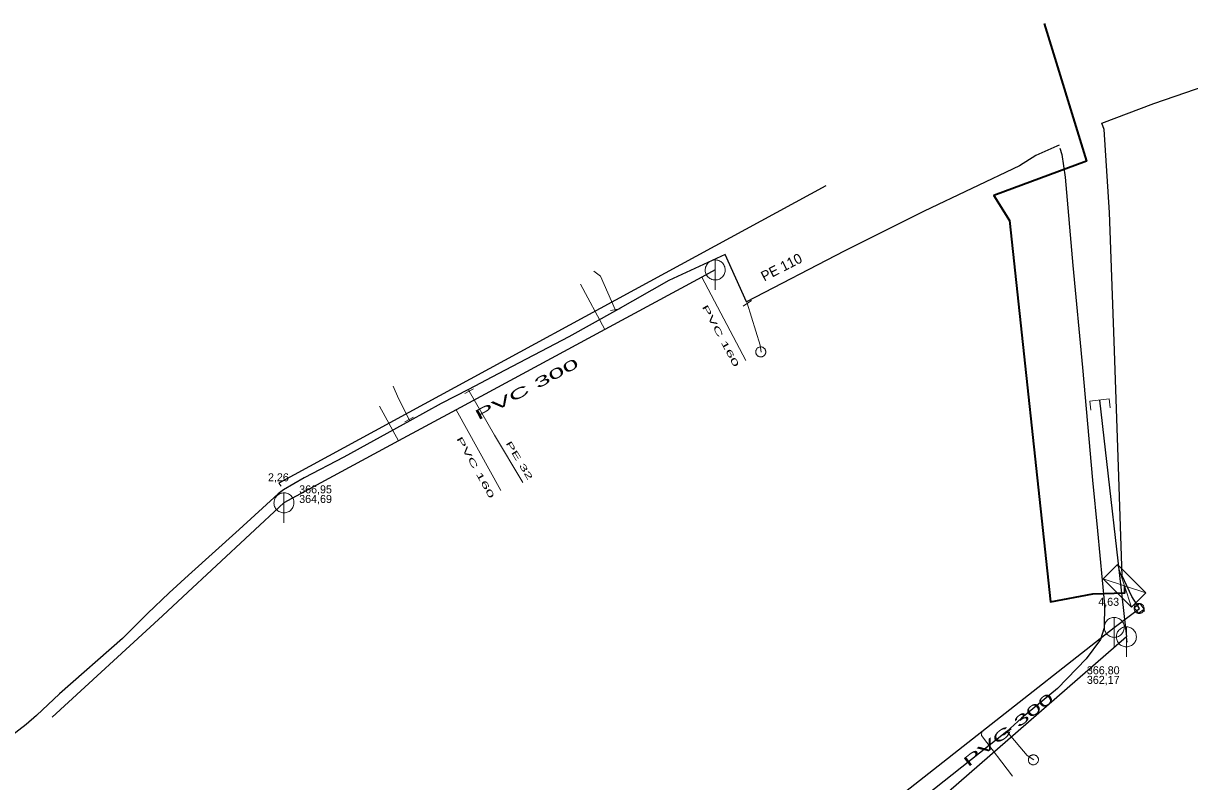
# Model space of a CAD drawing. Extents: x -809916 to -809489, y -991143 to -990912.
# Drawn here: x -809837.8 to -809721.2, y -990987.3 to -990911.5 of the extents above; entities that cross this region are included whole.
import ezdxf

# ---------------------------------------------------------------- set-up
doc = ezdxf.new("R2010")
doc.units = 0
doc.header["$LTSCALE"] = 0.32
doc.header["$PDMODE"] = 32
doc.header["$PDSIZE"] = 0.16
doc.layers.add('1', color=7, linetype='Continuous')
for name, color, linetype, lineweight in [('11', 7, 'Continuous', 13), ('13', 7, 'Continuous', 13), ('14', 7, 'Continuous', 25), ('17', 7, 'Continuous', 25), ('19', 7, 'Continuous', 13), ('22', 7, 'Continuous', 13), ('23', 7, 'Continuous', 13), ('31', 7, 'Continuous', 13), ('34', 7, 'Continuous', 13), ('4', 7, 'Continuous', 13)]:
    doc.layers.add(name, color=color, linetype=linetype, lineweight=lineweight)

msp = doc.modelspace()

# ---------------------------------------------------------------- linework, layer by layer
at = {"layer": '11'}
for p, q in [((-809765.559, -990945.19), (-809769.96, -990936.87)), ((-809782.09, -990937.559), (-809779.66, -990942.109)), ((-809802.17, -990949.76), (-809800.28, -990953.239)), ((-809790.05, -990958.199), (-809794.52, -990950.129)), ((-809812, -990957.75), (-809812.23, -990957.46)), ((-809727.44, -990973.35), (-809727.52, -990972.809))]:
    msp.add_line(p, q, dxfattribs=at)
at = {"layer": '11', "lineweight": 35}
msp.add_lwpolyline([(-809735.753, -990911.51), (-809731.52, -990925.268), (-809740.78, -990928.707), (-809739.192, -990931.221), (-809735.091, -990969.321), (-809730.858, -990968.527), (-809727.683, -990968.395), (-809727.683, -990967.733)], dxfattribs=at)
at = {"layer": '11'}
msp.add_lwpolyline([(-809738.899, -990986.73), (-809742.01, -990982.67), (-809741.98, -990982.27)], dxfattribs=at)
at = {"layer": '13'}
for points in [[(-809778.609, -990940.11), (-809780.1, -990936.78), (-809780.77, -990936.28)], [(-809765.41, -990939.48), (-809764.129, -990943.67), (-809764.039, -990944.359)], [(-809799.219, -990951.09), (-809800.28, -990949), (-809800.809, -990947.75)], [(-809793.219, -990948.26), (-809790.699, -990952.67), (-809787.84, -990957.379)], [(-809739.42, -990982.309), (-809737.44, -990984.66), (-809736.78, -990985.09)]]:
    msp.add_lwpolyline(points, dxfattribs=at)
at = {"layer": '14'}
for p, q in [((-809757.55, -990927.76), (-809812.23, -990957.46)), ((-809730.21, -990949.149), (-809727.52, -990972.809))]:
    msp.add_line(p, q, dxfattribs=at)
at = {"layer": '14', "lineweight": 13}
for p, q in [((-809765.5, -990939.35), (-809765.41, -990939.48)), ((-809778.59, -990940.219), (-809778.609, -990940.11)), ((-809793.3, -990948.11), (-809793.219, -990948.26)), ((-809799.219, -990951.09), (-809799.16, -990951.21)), ((-809739.469, -990982.25), (-809739.42, -990982.309))]:
    msp.add_line(p, q, dxfattribs=at)
at = {"layer": '14'}
for points in [[(-809726.219, -990969.96), (-809726.98, -990968.78), (-809727.949, -990966.71), (-809728.3, -990955.809), (-809728.739, -990943.25), (-809729.199, -990930.399), (-809729.739, -990922.109), (-809729.96, -990921.489), (-809724.76, -990919.53), (-809718.469, -990917.359), (-809710.05, -990914.129), (-809708.579, -990913.68), (-809706.219, -990913.69), (-809699.82, -990914.32), (-809692.859, -990914.989), (-809688.989, -990915.219), (-809679.469, -990915.67), (-809679.19, -990916.14), (-809678.829, -990917.93), (-809676.92, -990922.699), (-809676.27, -990924.289), (-809674.469, -990928.55)], [(-809768.62, -990936.149), (-809769.96, -990936.87), (-809779.66, -990942.109), (-809794.52, -990950.129), (-809800.28, -990953.239), (-809811.73, -990959.42)], [(-809811.73, -990959.42), (-809821.84, -990968.8), (-809823.879, -990970.699), (-809834.89, -990980.82)], [(-809728.73, -990971.86), (-809727.12, -990970.64), (-809726.219, -990969.96)], [(-809754.89, -990992.42), (-809741.98, -990982.27), (-809728.73, -990971.86)], [(-809727.52, -990972.809), (-809749.16, -990991.649), (-809753.69, -990995.359), (-809765.379, -991004.55)]]:
    msp.add_lwpolyline(points, dxfattribs=at)
at = {"layer": '17'}
for points in [[(-809734.239, -990923.69), (-809734.469, -990923.77), (-809736.57, -990924.73), (-809738.21, -990925.75), (-809747.719, -990930.27), (-809755.719, -990934.26), (-809765.5, -990939.35), (-809767.64, -990934.6)], [(-809734.16, -990923.969), (-809733.96, -990924.629), (-809733.649, -990926.879), (-809732.87, -990935.71), (-809731.899, -990945.899), (-809730.91, -990957.17), (-809730.39, -990962.23), (-809729.719, -990969.61), (-809729.73, -990971.899), (-809730.109, -990973.059), (-809731.53, -990975.01), (-809734.39, -990977.98), (-809737.989, -990980.949), (-809739.469, -990982.25), (-809748.46, -990989.399)], [(-809767.64, -990934.6), (-809773.26, -990937.219), (-809778.59, -990940.219), (-809783.25, -990942.84), (-809790.329, -990946.53), (-809793.3, -990948.11), (-809796.01, -990949.51), (-809799.16, -990951.21), (-809805.73, -990954.85), (-809809.719, -990956.93), (-809811.77, -990958.109), (-809812.32, -990958.52), (-809816.21, -990962.07), (-809821.28, -990966.66), (-809823.19, -990968.42), (-809825.359, -990970.469), (-809827.879, -990972.96), (-809834.17, -990978.5), (-809836.469, -990980.68), (-809837.489, -990981.55), (-809839.26, -990982.92)]]:
    msp.add_lwpolyline(points, dxfattribs=at)
at = {"layer": '19'}
for p, q in [((-809727.008, -990969.835), (-809728.411, -990965.578)), ((-809725.581, -990968.408), (-809729.838, -990967.005))]:
    msp.add_line(p, q, dxfattribs=at)
msp.add_lwpolyline([(-809727.008, -990969.835), (-809729.838, -990967.005), (-809728.411, -990965.578), (-809725.581, -990968.408)], close=True, dxfattribs=at)
at = {"layer": '22'}
for p, q in [((-809768.62, -990938.149), (-809768.619, -990935.149)), ((-809811.73, -990961.42), (-809811.729, -990958.42)), ((-809728.73, -990973.86), (-809728.729, -990970.86)), ((-809727.52, -990974.809), (-809727.519, -990971.809))]:
    msp.add_line(p, q, dxfattribs=at)
for points in [[(-809767.62, -990936.149), (-809767.625, -990936.04), (-809767.643, -990935.932), (-809767.673, -990935.826), (-809767.713, -990935.725), (-809767.765, -990935.628), (-809767.827, -990935.538), (-809767.899, -990935.455), (-809767.979, -990935.381), (-809768.067, -990935.315), (-809768.161, -990935.26), (-809768.261, -990935.215), (-809768.366, -990935.182), (-809768.473, -990935.16), (-809768.582, -990935.15), (-809768.692, -990935.152), (-809768.8, -990935.166), (-809768.907, -990935.191), (-809769.01, -990935.228), (-809769.108, -990935.277), (-809769.2, -990935.335), (-809769.286, -990935.404), (-809769.363, -990935.481), (-809769.432, -990935.567), (-809769.491, -990935.659), (-809769.539, -990935.757), (-809769.576, -990935.86), (-809769.602, -990935.967), (-809769.616, -990936.075), (-809769.619, -990936.185), (-809769.609, -990936.294), (-809769.588, -990936.401), (-809769.554, -990936.505), (-809769.51, -990936.605), (-809769.455, -990936.7), (-809769.389, -990936.788), (-809769.315, -990936.868), (-809769.232, -990936.94), (-809769.142, -990937.002), (-809769.046, -990937.054), (-809768.944, -990937.095), (-809768.839, -990937.125), (-809768.731, -990937.143), (-809768.621, -990937.149), (-809768.512, -990937.143), (-809768.404, -990937.125), (-809768.299, -990937.096), (-809768.197, -990937.055), (-809768.1, -990937.003), (-809768.01, -990936.941), (-809767.927, -990936.87), (-809767.852, -990936.79), (-809767.787, -990936.702), (-809767.731, -990936.608), (-809767.687, -990936.508), (-809767.653, -990936.404), (-809767.631, -990936.296), (-809767.621, -990936.187)], [(-809810.73, -990959.42), (-809810.735, -990959.311), (-809810.753, -990959.203), (-809810.783, -990959.097), (-809810.823, -990958.996), (-809810.875, -990958.899), (-809810.937, -990958.809), (-809811.009, -990958.726), (-809811.089, -990958.652), (-809811.177, -990958.586), (-809811.271, -990958.531), (-809811.371, -990958.486), (-809811.476, -990958.453), (-809811.583, -990958.431), (-809811.692, -990958.421), (-809811.802, -990958.423), (-809811.91, -990958.437), (-809812.017, -990958.462), (-809812.12, -990958.499), (-809812.218, -990958.548), (-809812.31, -990958.606), (-809812.396, -990958.675), (-809812.473, -990958.752), (-809812.542, -990958.838), (-809812.601, -990958.93), (-809812.649, -990959.028), (-809812.686, -990959.131), (-809812.712, -990959.238), (-809812.726, -990959.346), (-809812.729, -990959.456), (-809812.719, -990959.565), (-809812.698, -990959.672), (-809812.664, -990959.776), (-809812.62, -990959.876), (-809812.565, -990959.971), (-809812.499, -990960.059), (-809812.425, -990960.139), (-809812.342, -990960.211), (-809812.252, -990960.273), (-809812.156, -990960.325), (-809812.054, -990960.366), (-809811.949, -990960.396), (-809811.841, -990960.414), (-809811.731, -990960.42), (-809811.622, -990960.414), (-809811.514, -990960.396), (-809811.409, -990960.367), (-809811.307, -990960.326), (-809811.21, -990960.274), (-809811.12, -990960.212), (-809811.037, -990960.141), (-809810.962, -990960.061), (-809810.897, -990959.973), (-809810.841, -990959.879), (-809810.797, -990959.779), (-809810.763, -990959.675), (-809810.741, -990959.567), (-809810.731, -990959.458)], [(-809727.73, -990971.86), (-809727.735, -990971.751), (-809727.753, -990971.643), (-809727.783, -990971.537), (-809727.823, -990971.436), (-809727.875, -990971.339), (-809727.937, -990971.249), (-809728.009, -990971.166), (-809728.089, -990971.092), (-809728.177, -990971.026), (-809728.271, -990970.971), (-809728.371, -990970.926), (-809728.476, -990970.893), (-809728.583, -990970.871), (-809728.692, -990970.861), (-809728.802, -990970.863), (-809728.91, -990970.877), (-809729.017, -990970.902), (-809729.12, -990970.939), (-809729.218, -990970.988), (-809729.31, -990971.046), (-809729.396, -990971.115), (-809729.473, -990971.192), (-809729.542, -990971.278), (-809729.601, -990971.37), (-809729.649, -990971.468), (-809729.686, -990971.571), (-809729.712, -990971.678), (-809729.726, -990971.786), (-809729.729, -990971.896), (-809729.719, -990972.005), (-809729.698, -990972.112), (-809729.664, -990972.216), (-809729.62, -990972.316), (-809729.565, -990972.411), (-809729.499, -990972.499), (-809729.425, -990972.579), (-809729.342, -990972.651), (-809729.252, -990972.713), (-809729.156, -990972.765), (-809729.054, -990972.806), (-809728.949, -990972.836), (-809728.841, -990972.854), (-809728.731, -990972.86), (-809728.622, -990972.854), (-809728.514, -990972.836), (-809728.409, -990972.807), (-809728.307, -990972.766), (-809728.21, -990972.714), (-809728.12, -990972.652), (-809728.037, -990972.581), (-809727.962, -990972.501), (-809727.897, -990972.413), (-809727.841, -990972.319), (-809727.797, -990972.219), (-809727.763, -990972.115), (-809727.741, -990972.007), (-809727.731, -990971.898)], [(-809726.52, -990972.809), (-809726.525, -990972.7), (-809726.543, -990972.592), (-809726.573, -990972.486), (-809726.613, -990972.385), (-809726.665, -990972.288), (-809726.727, -990972.198), (-809726.799, -990972.115), (-809726.879, -990972.041), (-809726.967, -990971.975), (-809727.061, -990971.92), (-809727.161, -990971.875), (-809727.266, -990971.842), (-809727.373, -990971.82), (-809727.482, -990971.81), (-809727.592, -990971.812), (-809727.7, -990971.826), (-809727.807, -990971.851), (-809727.91, -990971.888), (-809728.008, -990971.937), (-809728.1, -990971.995), (-809728.186, -990972.064), (-809728.263, -990972.141), (-809728.332, -990972.227), (-809728.391, -990972.319), (-809728.439, -990972.417), (-809728.476, -990972.52), (-809728.502, -990972.627), (-809728.516, -990972.735), (-809728.519, -990972.845), (-809728.509, -990972.954), (-809728.488, -990973.061), (-809728.454, -990973.165), (-809728.41, -990973.265), (-809728.355, -990973.36), (-809728.289, -990973.448), (-809728.215, -990973.528), (-809728.132, -990973.6), (-809728.042, -990973.662), (-809727.946, -990973.714), (-809727.844, -990973.755), (-809727.739, -990973.785), (-809727.631, -990973.803), (-809727.521, -990973.809), (-809727.412, -990973.803), (-809727.304, -990973.785), (-809727.199, -990973.756), (-809727.097, -990973.715), (-809727, -990973.663), (-809726.91, -990973.601), (-809726.827, -990973.53), (-809726.752, -990973.45), (-809726.687, -990973.362), (-809726.631, -990973.268), (-809726.587, -990973.168), (-809726.553, -990973.064), (-809726.531, -990972.956), (-809726.521, -990972.847)]]:
    msp.add_lwpolyline(points, close=True, dxfattribs=at)
at = {"layer": '23'}
for points in [[(-809763.616, -990944.118), (-809763.64, -990944.074), (-809763.669, -990944.03), (-809763.706, -990943.99), (-809763.744, -990943.955), (-809763.786, -990943.923), (-809763.83, -990943.896), (-809763.877, -990943.875), (-809763.928, -990943.858), (-809763.978, -990943.846), (-809764.03, -990943.84), (-809764.082, -990943.84), (-809764.134, -990943.844), (-809764.186, -990943.853), (-809764.236, -990943.869), (-809764.285, -990943.889), (-809764.33, -990943.914), (-809764.371, -990943.945), (-809764.411, -990943.98), (-809764.448, -990944.018), (-809764.479, -990944.06), (-809764.506, -990944.105), (-809764.528, -990944.151), (-809764.545, -990944.202), (-809764.557, -990944.252), (-809764.562, -990944.305), (-809764.563, -990944.356), (-809764.559, -990944.408), (-809764.548, -990944.459), (-809764.534, -990944.51), (-809764.513, -990944.559), (-809764.487, -990944.604), (-809764.457, -990944.647), (-809764.424, -990944.686), (-809764.384, -990944.721), (-809764.344, -990944.753), (-809764.299, -990944.78), (-809764.25, -990944.803), (-809764.201, -990944.819), (-809764.15, -990944.831)], [(-809764.506, -990944.105), (-809764.528, -990944.151), (-809764.545, -990944.202), (-809764.557, -990944.252), (-809764.562, -990944.305), (-809764.563, -990944.356), (-809764.559, -990944.408), (-809764.548, -990944.459), (-809764.534, -990944.51), (-809764.513, -990944.559), (-809764.487, -990944.604), (-809764.457, -990944.647), (-809764.424, -990944.686), (-809764.384, -990944.721), (-809764.344, -990944.753), (-809764.299, -990944.78), (-809764.25, -990944.803), (-809764.201, -990944.819), (-809764.15, -990944.831), (-809764.098, -990944.836), (-809764.046, -990944.838), (-809763.994, -990944.834), (-809763.942, -990944.824), (-809763.892, -990944.808), (-809763.845, -990944.787), (-809763.799, -990944.762), (-809763.756, -990944.732), (-809763.717, -990944.697), (-809763.681, -990944.659), (-809763.65, -990944.617), (-809763.623, -990944.573), (-809763.601, -990944.525), (-809763.583, -990944.476), (-809763.572, -990944.424), (-809763.565, -990944.372), (-809763.565, -990944.321), (-809763.569, -990944.269), (-809763.58, -990944.216), (-809763.594, -990944.167), (-809763.616, -990944.118)], [(-809763.994, -990944.834), (-809763.942, -990944.824), (-809763.892, -990944.808), (-809763.845, -990944.787), (-809763.799, -990944.762), (-809763.756, -990944.732), (-809763.717, -990944.697), (-809763.681, -990944.659), (-809763.65, -990944.617), (-809763.623, -990944.573), (-809763.601, -990944.525), (-809763.583, -990944.476), (-809763.572, -990944.424), (-809763.565, -990944.372), (-809763.565, -990944.321), (-809763.569, -990944.269), (-809763.58, -990944.216), (-809763.594, -990944.167), (-809763.616, -990944.118), (-809763.64, -990944.074), (-809763.669, -990944.03), (-809763.706, -990943.99), (-809763.744, -990943.955), (-809763.786, -990943.923), (-809763.83, -990943.896), (-809763.877, -990943.875), (-809763.928, -990943.858), (-809763.978, -990943.846), (-809764.03, -990943.84), (-809764.082, -990943.84), (-809764.134, -990943.844), (-809764.186, -990943.853), (-809764.236, -990943.869), (-809764.285, -990943.889), (-809764.33, -990943.914), (-809764.371, -990943.945), (-809764.411, -990943.98), (-809764.448, -990944.018), (-809764.479, -990944.06), (-809764.506, -990944.105)], [(-809764.15, -990944.831), (-809764.098, -990944.836), (-809764.046, -990944.838), (-809763.994, -990944.834)], [(-809736.389, -990985.365), (-809736.363, -990985.319), (-809736.342, -990985.27), (-809736.328, -990985.221), (-809736.317, -990985.169), (-809736.312, -990985.118), (-809736.313, -990985.064), (-809736.319, -990985.013), (-809736.33, -990984.963), (-809736.347, -990984.913), (-809736.368, -990984.865), (-809736.395, -990984.819), (-809736.427, -990984.777), (-809736.461, -990984.739), (-809736.5, -990984.705), (-809736.542, -990984.674), (-809736.59, -990984.648), (-809736.636, -990984.627), (-809736.688, -990984.612), (-809736.737, -990984.601), (-809736.789, -990984.595), (-809736.843, -990984.597), (-809736.895, -990984.603), (-809736.946, -990984.615), (-809736.996, -990984.63), (-809737.043, -990984.653), (-809737.088, -990984.68), (-809737.129, -990984.711), (-809737.168, -990984.746), (-809737.202, -990984.786), (-809737.233, -990984.828), (-809737.259, -990984.873), (-809737.28, -990984.922), (-809737.296, -990984.972), (-809737.306, -990985.023), (-809737.31, -990985.074), (-809737.31, -990985.127), (-809737.304, -990985.179), (-809737.293, -990985.231), (-809737.276, -990985.28)], [(-809736.688, -990984.612), (-809736.737, -990984.601), (-809736.789, -990984.595), (-809736.843, -990984.597), (-809736.895, -990984.603), (-809736.946, -990984.615), (-809736.996, -990984.63), (-809737.043, -990984.653), (-809737.088, -990984.68), (-809737.129, -990984.711), (-809737.168, -990984.746), (-809737.202, -990984.786), (-809737.233, -990984.828), (-809737.259, -990984.873), (-809737.28, -990984.922), (-809737.296, -990984.972), (-809737.306, -990985.023), (-809737.31, -990985.074), (-809737.31, -990985.127), (-809737.304, -990985.179), (-809737.293, -990985.231), (-809737.276, -990985.28), (-809737.255, -990985.327), (-809737.228, -990985.372), (-809737.198, -990985.414), (-809737.161, -990985.453), (-809737.122, -990985.487), (-809737.08, -990985.517), (-809737.034, -990985.542), (-809736.986, -990985.564), (-809736.936, -990985.58), (-809736.885, -990985.59), (-809736.832, -990985.595), (-809736.781, -990985.595), (-809736.728, -990985.588), (-809736.678, -990985.578), (-809736.628, -990985.561), (-809736.579, -990985.539), (-809736.535, -990985.512), (-809736.493, -990985.481)], [(-809737.276, -990985.28), (-809737.255, -990985.327), (-809737.228, -990985.372), (-809737.198, -990985.414), (-809737.161, -990985.453), (-809737.122, -990985.487), (-809737.08, -990985.517), (-809737.034, -990985.542), (-809736.986, -990985.564), (-809736.936, -990985.58), (-809736.885, -990985.59), (-809736.832, -990985.595), (-809736.781, -990985.595), (-809736.728, -990985.588), (-809736.678, -990985.578), (-809736.628, -990985.561), (-809736.579, -990985.539), (-809736.535, -990985.512), (-809736.493, -990985.481), (-809736.455, -990985.445), (-809736.42, -990985.406), (-809736.389, -990985.365), (-809736.363, -990985.319), (-809736.342, -990985.27), (-809736.328, -990985.221), (-809736.317, -990985.169), (-809736.312, -990985.118), (-809736.313, -990985.064), (-809736.319, -990985.013), (-809736.33, -990984.963), (-809736.347, -990984.913), (-809736.368, -990984.865), (-809736.395, -990984.819), (-809736.427, -990984.777), (-809736.461, -990984.739), (-809736.5, -990984.705), (-809736.542, -990984.674), (-809736.59, -990984.648), (-809736.636, -990984.627), (-809736.688, -990984.612)], [(-809736.493, -990985.481), (-809736.455, -990985.445), (-809736.42, -990985.406), (-809736.389, -990985.365)]]:
    msp.add_lwpolyline(points, dxfattribs=at)
at = {"layer": '31'}
msp.add_lwpolyline([(-809729.148, -990949.934), (-809729.25, -990949.039), (-809731.169, -990949.257), (-809731.068, -990950.152)], dxfattribs=at)
at = {"layer": '34'}
for p, q in [((-809764.999, -990939.194), (-809765.821, -990939.764)), ((-809779.1, -990940.199), (-809778.116, -990940.021)), ((-809792.778, -990948.024), (-809793.66, -990948.494)), ((-809799.664, -990951.316), (-809798.772, -990950.864)), ((-809739.036, -990981.988), (-809739.804, -990982.628))]:
    msp.add_line(p, q, dxfattribs=at)
at = {"layer": '4'}
for points in [[(-809725.849, -990969.67), (-809725.882, -990969.63), (-809725.922, -990969.593), (-809725.963, -990969.561), (-809726.007, -990969.533), (-809726.054, -990969.511), (-809726.105, -990969.493), (-809726.154, -990969.48), (-809726.206, -990969.475), (-809726.258, -990969.471), (-809726.311, -990969.474), (-809726.363, -990969.484), (-809726.412, -990969.5), (-809726.461, -990969.518), (-809726.508, -990969.543), (-809726.549, -990969.573), (-809726.589, -990969.606), (-809726.626, -990969.645), (-809726.659, -990969.686), (-809726.687, -990969.73), (-809726.708, -990969.777), (-809726.726, -990969.827), (-809726.739, -990969.877), (-809726.746, -990969.93), (-809726.749, -990969.981), (-809726.745, -990970.033), (-809726.735, -990970.086), (-809726.721, -990970.135), (-809726.702, -990970.184), (-809726.675, -990970.23), (-809726.646, -990970.272), (-809726.613, -990970.312), (-809726.574, -990970.349), (-809726.534, -990970.383), (-809726.489, -990970.409), (-809726.442, -990970.431), (-809726.393, -990970.45), (-809726.342, -990970.462), (-809726.291, -990970.47), (-809726.238, -990970.471), (-809726.186, -990970.468), (-809726.134, -990970.458), (-809726.084, -990970.444), (-809726.035, -990970.424), (-809725.989, -990970.399), (-809725.947, -990970.37), (-809725.907, -990970.337), (-809725.87, -990970.297), (-809725.838, -990970.258), (-809725.811, -990970.212), (-809725.788, -990970.165), (-809725.769, -990970.116), (-809725.757, -990970.066), (-809725.751, -990970.014), (-809725.748, -990969.962), (-809725.751, -990969.909), (-809725.761, -990969.856), (-809725.775, -990969.808), (-809725.795, -990969.759), (-809725.82, -990969.712)], [(-809726.739, -990969.903), (-809726.174, -990969.476), (-809725.755, -990970.029), (-809726.321, -990970.456)]]:
    msp.add_lwpolyline(points, close=True, dxfattribs=at)
msp.add_point((-809725.799, -990970.193), dxfattribs=at)

# ---------------------------------------------------------------- texts
at = {"layer": '1'}
msp.add_text('PE 110', height=1, rotation=27, dxfattribs=at).set_placement((-809763.725, -990937.315))
for s, height, rotation, width, p in [('PVC 160 ', 0.6, 298, 2.15, (-809769.97, -990939.823)), ('PVC 300 ', 1, 28, 2.15, (-809792.311, -990951.194)), ('PVC 160 ', 0.6, 299, 2.15, (-809794.518, -990953.001)), ('PE 32 ', 0.6, 301, 2, (-809789.584, -990953.461)), ('PVC 300 ', 1, 38, 2.05, (-809743.334, -990985.862))]:
    msp.add_text(s, height=height, rotation=rotation, dxfattribs=dict(at, width=width)).set_placement(p)
for s, p in [('2,26', (-809813.33, -990957.267)), ('4,63', (-809730.33, -990969.707))]:
    msp.add_text(s, height=0.8, dxfattribs=at).set_placement(p)
at = {"layer": '19'}
for s, p in [('366,95', (-809810.208, -990958.471)), ('364,69', (-809810.208, -990959.431)), ('366,80', (-809731.467, -990976.547)), ('362,17', (-809731.467, -990977.507))]:
    msp.add_text(s, height=0.8, dxfattribs=at).set_placement(p)

doc.saveas('drawing.dxf')
